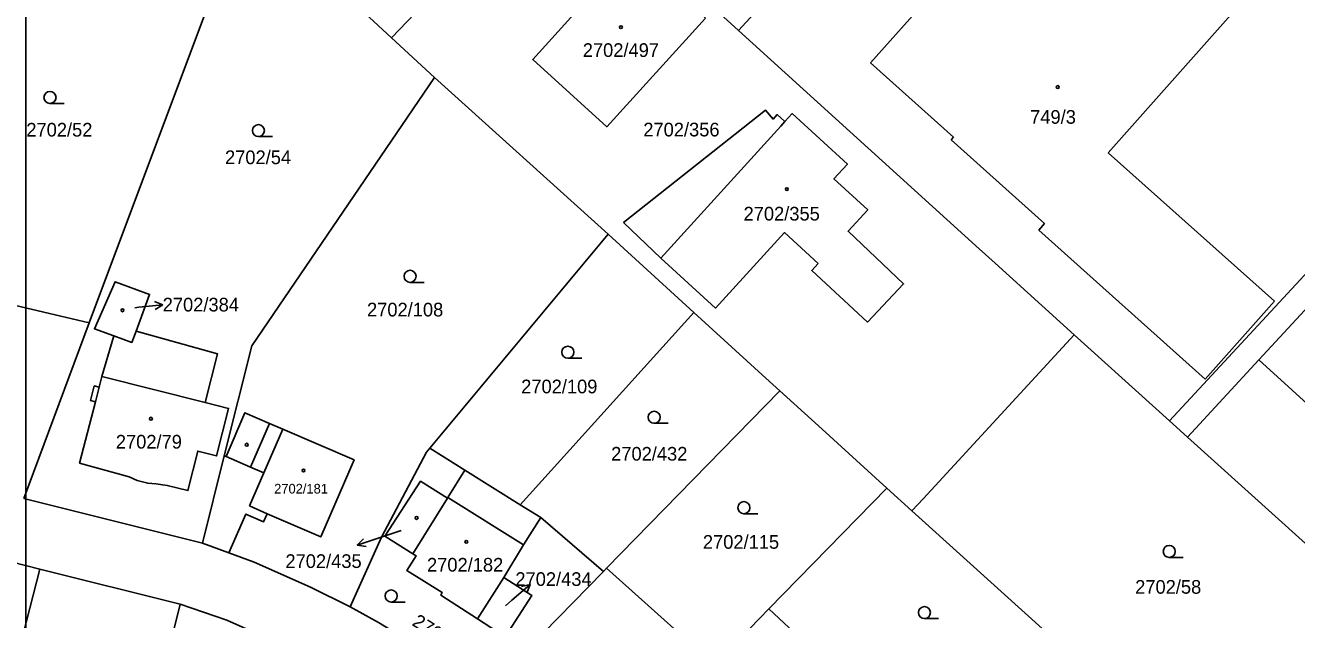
# Model space of a CAD drawing. Extents: x -496682 to -495907, y -1088575 to -1088018.
# Drawn here: x -496557.4 to -496399.3, y -1088434.5 to -1088360.6 of the extents above; entities that cross this region are included whole.
import ezdxf

# ---------------------------------------------------------------- set-up
doc = ezdxf.new("R2010")
doc.units = 0
for name, color, linetype in [('Hranice parcel', 7, 'Continuous'), ('Parcelní čísla', 7, 'Continuous'), ('Pop  PČ popisy', 7, 'Continuous'), ('Vnitřní kresba', 7, 'Continuous'), ('Vrstva 63', 7, 'Continuous'), ('Značky budov', 7, 'Continuous'), ('Značky kultur', 7, 'Continuous')]:
    doc.layers.add(name, color=color, linetype=linetype)

msp = doc.modelspace()

# ---------------------------------------------------------------- linework, layer by layer
at = {"layer": 'Hranice parcel'}
for p, q in [((-496468.73, -1088361.18), (-496495.35, -1088337)), ((-496511.87, -1088362.1), (-496529.95, -1088345.34)), ((-496549.47, -1088397.55), (-496534.41, -1088357.28)), ((-496506.52, -1088367.06), (-496511.87, -1088362.1)), ((-496484.94, -1088386.51), (-496506.52, -1088367.06)), ((-496415.13, -1088409.73), (-496376.05, -1088367.51)), ((-496507.11, -1088413.15), (-496484.94, -1088386.51)), ((-496474.27, -1088396.26), (-496484.94, -1088386.51)), ((-496495.87, -1088420.18), (-496474.27, -1088396.26)), ((-496557.63, -1088419.38), (-496549.47, -1088397.55)), ((-496426.99, -1088399.03), (-496415.13, -1088409.73)), ((-496463.6, -1088406), (-496485.14, -1088428.06)), ((-496535.38, -1088424.94), (-496532.68, -1088414.09)), ((-496507.11, -1088413.15), (-496502.75, -1088415.88)), ((-496502.75, -1088415.88), (-496495.87, -1088420.18)), ((-496557.63, -1088419.38), (-496535.38, -1088424.94)), ((-496504.92, -1088419.36), (-496509.22, -1088426.26)), ((-496450.29, -1088418.11), (-496464.95, -1088433.12)), ((-496447.16, -1088420.94), (-496450.29, -1088418.11)), ((-496493.32, -1088421.78), (-496495.87, -1088420.18)), ((-496428.41, -1088437.89), (-496447.16, -1088420.94)), ((-496580.96, -1088421.7), (-496555.62, -1088428.18)), ((-496493.32, -1088421.78), (-496485.53, -1088428.46)), ((-496532.1, -1088426.15), (-496535.38, -1088424.94)), ((-496555.62, -1088428.18), (-496538.16, -1088432.53)), ((-496485.53, -1088428.46), (-496500.3, -1088443.59)), ((-496485.14, -1088428.06), (-496485.53, -1088428.46)), ((-496471.71, -1088440.06), (-496485.14, -1088428.06)), ((-496501.2, -1088434.35), (-496497.9, -1088429.23)), ((-496538.16, -1088432.53), (-496542.82, -1088451.3)), ((-496464.95, -1088433.12), (-496471.71, -1088440.06))]:
    msp.add_line(p, q, dxfattribs=at)
for points in [[(-496495.35, -1088337), (-496495.31, -1088344.8), (-496511.87, -1088362.1)], [(-496445.51, -1088336.16), (-496449.94, -1088340.76), (-496468.73, -1088361.18)], [(-496472.85, -1088359.67), (-496485.1, -1088373.16), (-496494.32, -1088364.79), (-496482.11, -1088351.3), (-496472.85, -1088359.67)], [(-496468.73, -1088361.18), (-496438.82, -1088388.34), (-496436.83, -1088390.15), (-496426.99, -1088399.03)], [(-496532.68, -1088414.09), (-496529.27, -1088400.43), (-496506.52, -1088367.06)], [(-496458.81, -1088390.16), (-496459.62, -1088391.05), (-496452.7, -1088397.45), (-496448.2, -1088392.71), (-496455.1, -1088386.16), (-496452.66, -1088383.51), (-496456.87, -1088379.65), (-496455.18, -1088377.81), (-496462.05, -1088371.53), (-496462.96, -1088372.53), (-496463.92, -1088371.65), (-496464.44, -1088372.21), (-496465.37, -1088371.11), (-496483.02, -1088385.08), (-496478.41, -1088389.5), (-496471.58, -1088395.72), (-496463.03, -1088386.33), (-496458.81, -1088390.16)], [(-496574.52, -1088391.68), (-496554.43, -1088396.39), (-496549.47, -1088397.55)], [(-496546.43, -1088399.15), (-496548.84, -1088398.28), (-496546.26, -1088392.45), (-496541.98, -1088394.02), (-496543.65, -1088398.6)], [(-496474.27, -1088396.26), (-496465.34, -1088404.42), (-496463.6, -1088406)], [(-496543.65, -1088398.6), (-496533.53, -1088401.39), (-496535.05, -1088407.46), (-496532.14, -1088408.2), (-496533.63, -1088414.1), (-496535.98, -1088413.51), (-496537.21, -1088418.41), (-496539.77, -1088417.78), (-496541.18, -1088417.56), (-496542.21, -1088417.51), (-496543.51, -1088417.18), (-496544.5, -1088416.71), (-496550.68, -1088415.02), (-496548.71, -1088407.38), (-496549.32, -1088407.23), (-496548.85, -1088405.39), (-496548.24, -1088405.55), (-496547.9, -1088404.23), (-496546.43, -1088399.15)], [(-496543.65, -1088398.6), (-496544.16, -1088399.98), (-496546.43, -1088399.15)], [(-496426.99, -1088399.03), (-496445.74, -1088419.4), (-496447.16, -1088420.94)], [(-496450.29, -1088418.11), (-496458.79, -1088410.38), (-496463.6, -1088406)], [(-496532.68, -1088414.09), (-496532.43, -1088414.19), (-496530.13, -1088408.73), (-496527.05, -1088410.06), (-496525.42, -1088410.77), (-496516.55, -1088414.6), (-496520.69, -1088424.17), (-496527.35, -1088421.29), (-496527.79, -1088422.29), (-496530.01, -1088421.34), (-496532.1, -1088426.15)], [(-496415.13, -1088409.73), (-496412.88, -1088411.76), (-496391.09, -1088431.4)], [(-496517.03, -1088432.88), (-496513.11, -1088424.21), (-496507.54, -1088413.62), (-496507.11, -1088413.15)], [(-496502.75, -1088415.88), (-496504.86, -1088419.27), (-496504.92, -1088419.36)], [(-496509.22, -1088426.26), (-496512.71, -1088424.09), (-496508.27, -1088417.26), (-496504.92, -1088419.36)], [(-496497.9, -1088429.23), (-496495.45, -1088425.18), (-496493.32, -1088421.78)], [(-496517.03, -1088432.88), (-496521.97, -1088430.43), (-496528.95, -1088427.3), (-496532.1, -1088426.15)], [(-496509.22, -1088426.26), (-496508.83, -1088426.51), (-496509.96, -1088428.37), (-496505.58, -1088431.1), (-496505.77, -1088431.4), (-496501.2, -1088434.35)], [(-496555.62, -1088428.18), (-496558.12, -1088437.89), (-496559.72, -1088444.15), (-496560.5, -1088447.06)], [(-496497.9, -1088429.23), (-496494.43, -1088431.47), (-496497.73, -1088436.59), (-496501.2, -1088434.35)], [(-496538.16, -1088432.53), (-496532.37, -1088434.53), (-496526.9, -1088436.97), (-496519.8, -1088440.54)], [(-496500.3, -1088443.59), (-496505.39, -1088439.93), (-496508.83, -1088437.68), (-496513.52, -1088434.81), (-496517.03, -1088432.88)], [(-496464.95, -1088433.12), (-496451.1, -1088446.07), (-496456.7, -1088452.55)]]:
    msp.add_lwpolyline(points, dxfattribs=at)
at = {"layer": 'Pop  PČ popisy'}
for p, q in [((-496543.82, -1088395.67), (-496543.32, -1088395.62)), ((-496543.32, -1088395.62), (-496540.34, -1088395.31)), ((-496540.34, -1088395.31), (-496541.38, -1088394.91)), ((-496540.34, -1088395.31), (-496541.28, -1088395.91)), ((-496510.7, -1088423.39), (-496513.29, -1088424.26)), ((-496513.29, -1088424.26), (-496516.14, -1088425.19)), ((-496516.14, -1088425.19), (-496515.35, -1088424.4)), ((-496516.14, -1088425.19), (-496515.04, -1088425.35)), ((-496496.91, -1088432.05), (-496494.65, -1088430.08)), ((-496494.65, -1088430.08), (-496495.73, -1088430.36)), ((-496494.65, -1088430.08), (-496495.07, -1088431.12)), ((-496497.7, -1088432.75), (-496496.91, -1088432.05))]:
    msp.add_line(p, q, dxfattribs=at)
at = {"layer": 'Vnitřní kresba'}
for p, q in [((-496452.33, -1088365.21), (-496439.78, -1088351.18)), ((-496399.46, -1088350.2), (-496422.76, -1088376.41)), ((-496441.98, -1088374.47), (-496452.33, -1088365.21)), ((-496404.03, -1088402.17), (-496375.12, -1088370.85)), ((-496478.41, -1088389.5), (-496463.48, -1088373.09)), ((-496463.48, -1088373.09), (-496462.96, -1088372.53)), ((-496442.28, -1088374.81), (-496441.98, -1088374.47)), ((-496430.67, -1088385.21), (-496442.28, -1088374.81)), ((-496422.76, -1088376.41), (-496402.05, -1088394.84)), ((-496431.4, -1088386.04), (-496430.67, -1088385.21)), ((-496410.7, -1088404.57), (-496431.4, -1088386.04)), ((-496402.05, -1088394.84), (-496410.7, -1088404.57)), ((-496412.88, -1088411.76), (-496404.03, -1088402.17)), ((-496391.38, -1088413.68), (-496404.03, -1088402.17)), ((-496547.9, -1088404.23), (-496535.05, -1088407.46)), ((-496548.24, -1088405.55), (-496548.71, -1088407.38)), ((-496527.05, -1088410.06), (-496529.41, -1088415.51)), ((-496525.42, -1088410.77), (-496527.78, -1088416.21)), ((-496529.41, -1088415.51), (-496532.43, -1088414.19)), ((-496529.55, -1088420.29), (-496527.78, -1088416.21)), ((-496527.78, -1088416.21), (-496529.41, -1088415.51)), ((-496495.45, -1088425.18), (-496504.86, -1088419.27)), ((-496529.55, -1088420.29), (-496527.35, -1088421.29))]:
    msp.add_line(p, q, dxfattribs=at)
at = {"layer": 'Vrstva 63'}
msp.add_lwpolyline([(-496137.35, -1088164.24), (-496137.35, -1088461.24), (-496557.35, -1088461.24), (-496557.35, -1088164.24)], close=True, dxfattribs=at)
at = {"layer": 'Značky budov'}
for centre in [(-496483.35, -1088360.79), (-496429.03, -1088368.23), (-496462.71, -1088380.92), (-496545.33, -1088395.99), (-496541.8, -1088409.48), (-496529.89, -1088412.71), (-496522.82, -1088415.91), (-496508.76, -1088421.82), (-496502.58, -1088424.78)]:
    msp.add_circle(centre, 0.175, dxfattribs=at)
at = {"layer": 'Značky kultur'}
for p, q in [((-496554.36, -1088370.27), (-496552.61, -1088370.27)), ((-496528.44, -1088374.4), (-496526.69, -1088374.4)), ((-496509.58, -1088392.52), (-496507.83, -1088392.52)), ((-496489.95, -1088401.96), (-496488.2, -1088401.96)), ((-496479.22, -1088410.05), (-496477.47, -1088410.05)), ((-496468.06, -1088421.29), (-496466.31, -1088421.29)), ((-496415.16, -1088426.73), (-496413.41, -1088426.73)), ((-496511.93, -1088432.27), (-496510.18, -1088432.27)), ((-496445.61, -1088434.34), (-496443.86, -1088434.34))]:
    msp.add_line(p, q, dxfattribs=at)
for centre in [(-496554.36, -1088369.52), (-496528.44, -1088373.65), (-496509.58, -1088391.77), (-496489.95, -1088401.21), (-496479.22, -1088409.3), (-496468.06, -1088420.54), (-496415.16, -1088425.98), (-496511.93, -1088431.52), (-496445.61, -1088433.59)]:
    msp.add_circle(centre, 0.75, dxfattribs=at)

# ---------------------------------------------------------------- texts
at = {"layer": 'Parcelní čísla'}
for s, height, p in [('2702/497', 1.7, (-496488.1, -1088364.49)), ('749/3', 1.7, (-496432.46, -1088372.8)), ('2702/52', 1.7, (-496557.3, -1088374.39)), ('2702/356', 1.7, (-496480.57, -1088374.37)), ('2702/54', 1.7, (-496532.59, -1088377.82)), ('2702/355', 1.7, (-496468.1, -1088384.83)), ('2702/384', 1.7, (-496540.34, -1088396.14)), ('2702/108', 1.7, (-496514.93, -1088396.76)), ('2702/109', 1.7, (-496495.76, -1088406.32)), ('2702/79', 1.7, (-496546.17, -1088413.19)), ('2702/432', 1.7, (-496484.57, -1088414.69)), ('2702/181', 1.2, (-496526.48, -1088418.78)), ('2702/115', 1.7, (-496473.16, -1088425.65)), ('2702/435', 1.7, (-496525.08, -1088428.04)), ('2702/182', 1.7, (-496507.47, -1088428.49)), ('2702/434', 1.7, (-496496.48, -1088430.27)), ('2702/58', 1.7, (-496419.4, -1088431.24))]:
    msp.add_text(s, height=height, dxfattribs=at).set_placement(p)
msp.add_text('2702/433', height=1.7, rotation=327, dxfattribs=at).set_placement((-496509.44, -1088435.09))

doc.saveas('drawing.dxf')
